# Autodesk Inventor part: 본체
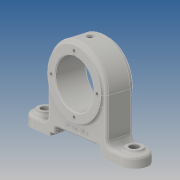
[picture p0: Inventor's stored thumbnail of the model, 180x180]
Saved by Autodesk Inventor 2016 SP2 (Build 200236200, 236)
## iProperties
Created: 2019-05
Part Number: 본체
Material: Generic
Document SubType Name: Modeling
Designer: EZ
Density: 1 g/cm^3
Appearance: Default
Mass: 168.276 g
Surface Area: 320.121 cm^2
Volume: 168.276 cm^3
Author: EZ
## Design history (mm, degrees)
sketch "스케치1"
  geometry: L1 (75, 15)-(60, 15); L2 (-75, 15)-(-75, 0); L3 (-75, -15)-(-60, -15); L4 (75, -15)-(75, 0); L5 (75, 15)-(-75, -15); L6 (-75, 15)-(75, -15); L7 (60, -15)-(75, -15); L8 (75, 0)-(75, 15); L9 (60, 15)-(-60, 15); L10 (-60, -15)-(60, -15); L11 (-75, 0)-(-75, -15); L12 (-60, 15)-(-75, 15); A1 r 15 centre (60, 0) between (60, -15) and (60, 15); A2 r 15 centre (-60, 0) between (-60, 15) and (-60, -15); 3 further points
  constraints: 24 end point, 13 parallel, 6 perpendicular, 6 point on circle, 4 midpoint, 4 tangent, 3 horizontal, 2 centre point, 2 horizontal alignment
  dimensions: "d0" = 150 distance of L4.start L3.start; "d1" = 30 distance of L3.start L2.start; "d2" = 30 diameter of A1; "d3" = 30 diameter of A2
extrude "돌출1" new body sketch "스케치1" distance "d4" = 12; taper "d5" = 0 deg
sketch "스케치2"
  geometry: L1 (24, -4)-(96, -4); L2 (96, -4)-(96, 4); L3 (96, 4)-(24, 4); L4 (24, 4)-(24, -4); L5 (24, -4)-(96, 4); L6 (96, -4)-(24, 4); L7 (0, 0)-(120, 0) reference; 1 further point
  constraints: 12 end point, 2 midpoint, 2 parallel, 1 horizontal, 1 perpendicular
  dimensions: "d6" = 72 distance of L3.end L2.end; "d7" = 4 distance between parallel lines of L7 L3
extrude "돌출2" cut sketch "스케치2" stored distance "d8" = 12; taper "d9" = 0 deg
sketch "스케치3"
  geometry: L1 (30, -22)-(90, -22); L2 (90, -22)-(90, -2); L3 (90, -2)-(30, -2); L4 (30, -2)-(30, -22); L5 (30, -22)-(90, -2); L6 (90, -22)-(30, -2); L7 (96, -12)-(120, -12) reference; 1 further point
  constraints: 12 end point, 2 midpoint, 2 parallel, 1 horizontal, 1 perpendicular
  dimensions: "d10" = 60 distance of L3.end L2.end; "d11" = 10 distance between parallel lines of L7 L3
extrude "돌출3" cut sketch "스케치3" stored distance "d12" = 12; taper "d13" = 0 deg
sketch "스케치4"
  geometry: L1 (-60, -15)-(60, -15) reference; L2 (60, 15)-(-60, 15) reference; C1 r 9 at (-60, 0); C2 r 9 at (60, 0); A1 r 15 centre (-60, 0) between (-60, 15) and (-60, -15) reference; A2 r 15 centre (60, 0) between (60, -15) and (60, 15) reference; 1 further point
  constraints: 2 centre point, 2 coincident
  dimensions: "d14" = 18 diameter of C1; "d15" = 18 diameter of C2
extrude "돌출4" join sketch "스케치4" distance "d16" = 3; taper "d17" = 0 deg
hole "구멍1" diameter "d20" = 11; stored, may be unused: countersink angle "d24" = 90 deg, drill point angle "d26" = 118 deg; dims "d21" = 6, "d22" = 4, "d23" = 2, "d25" = 8, "d27" = 10, "d28" = 10
sketch "스케치5"
  geometry: L1 (-36, 0)-(-60, 0) reference; C1 r 40 at (0, 60); 1 further point
  constraints: 1 centre point, 1 vertical alignment
  dimensions: "d29" = 60 distance from line of C1.centre L1; "d30" = 100 dimension on C1 L1
extrude "돌출5" join sketch "스케치5" stored distance "d31" = 30; taper "d32" = 0 deg
sketch "스케치6"
  geometry: L1 (30, 4)-(30, 10) reference; L2 (30, 10)-(-30, 10) reference; L3 (-30, 10)-(-30, 4) reference; L4 (-30, 4)-(-36, 4) reference; L5 (-36, 4)-(-36, 0) reference; L6 (-36, 0)-(-60, 0) reference; L7 (-60, 0)-(-60, 12) reference; L8 (60, 12)-(-60, 12) reference; L9 (60, 0)-(60, 12) reference; L10 (60, 0)-(36, 0) reference; L11 (36, 0)-(36, 4) reference; L12 (36, 4)-(30, 4) reference; L13 (-40, 60)-(-40, 12); L14 (40, 60)-(40, 12); A1 r 40 centre (0, 60) between (-40, 60) and (40, 60) reference; 1 further point
  constraints: 4 end point, 2 point on circle, 2 point on line, 2 tangent, 1 perpendicular, 1 vertical
extrude "돌출6" join sketch "스케치6" stored distance "d33" = 30; taper "d34" = 0 deg
sketch "스케치7"
  geometry: L1 (30, 4)-(30, 10) reference; L2 (30, 10)-(-30, 10) reference; L3 (-30, 10)-(-30, 4) reference; L4 (-30, 4)-(-36, 4) reference; L5 (-36, 4)-(-36, 0) reference; L6 (-36, 0)-(-60, 0) reference; L7 (-60, 0)-(-60, 12) reference; L8 (-40, 12)-(-60, 12) reference; L9 (-40, 12)-(-40, 60) reference; L10 (40, 60)-(40, 12) reference; L11 (60, 12)-(40, 12) reference; L12 (60, 0)-(60, 12) reference; L13 (60, 0)-(36, 0) reference; L14 (36, 0)-(36, 4) reference; L15 (36, 4)-(30, 4) reference; C1 r 36 at (0, 60); A1 r 40 centre (0, 60) between (40, 60) and (-40, 60) reference; 1 further point
  constraints: 1 centre point, 1 coincident
  dimensions: "d35" = 72 diameter of C1
extrude "돌출7" join sketch "스케치7" stored distance "d36" = 36; taper "d37" = 0 deg
hole "구멍2" diameter "d40" = 52; stored, may be unused: countersink angle "d44" = 90 deg, drill point angle "d46" = 118 deg; dims "d38" = 10, "d39" = 10, "d41" = 6, "d42" = 4, "d43" = 2, "d45" = 8
sketch "스케치8"
  geometry: C1 r 26 at (0, 0) reference; C2 r 36 at (0, 0) reference; A1 r 31 centre (0, 0) between (0, 31) and (0, -31); 3 further points
  constraints: 4 point on circle, 2 horizontal alignment, 2 vertical alignment, 1 centre point, 1 coincident
  dimensions: "d47" = 62 diameter of A1
hole "구멍3" sketch "스케치8" at (0, 31), (0, -31), (31, 0), (-31, 0) diameter "d48" = 3.242; stored, may be unused: countersink angle "d52" = 90 deg, drill point angle "d54" = 118 deg; dims "d49" = 6, "d50" = 4, "d51" = 2, "d53" = 8
node "작업 평면1"
sketch "스케치9"
  geometry: 2 further points
  constraints: 1 coincident
hole "구멍4" sketch "스케치9" at (0, 0) diameter "d56" = 7; stored, may be unused: countersink angle "d60" = 90 deg, drill point angle "d62" = 0 deg; dims "d57" = 6, "d58" = 7, "d59" = 2, "d61" = 1
hole "구멍5" diameter "d65" = 4.917; stored, may be unused: countersink angle "d69" = 90 deg, drill point angle "d71" = 118 deg; dims "d66" = 7, "d67" = 7, "d68" = 2, "d70" = 9, "d103" = 10, "d104" = 10
hole "구멍6" diameter "d74" = 2; stored, may be unused: countersink angle "d78" = 90 deg, drill point angle "d80" = 118 deg; dims "d75" = 2, "d76" = 7, "d77" = 2, "d79" = 10, "d81" = 10, "d82" = 10
fillet "모깎기1" dims "d86" = 6
fillet "모깎기2" dims "d87" = 3
fillet "모깎기3" dims "d88" = 3
fillet "모깎기4" dims "d89" = 3
sketch "스케치10"
  geometry: 3 further points
  constraints: 2 vertical alignment, 1 other
hole "구멍7" sketch "스케치10" at (0, 86) diameter "d90" = 3; stored, may be unused: countersink angle "d94" = 90 deg, drill point angle "d96" = 118 deg; dims "d91" = 2, "d92" = 7, "d93" = 2, "d95" = 10
chamfer "모따기2" distance "d97" = 1; stored, may be unused: second distance "d98" = 2, angle "d99" = 45 deg
sketch "스케치11"
  geometry: L1 (33, 10)-(87, 10) reference; 2 further points
  constraints: 1 vertical alignment, 1 other
  dimensions: "d100" = 7 distance from line of point (60, 17) L1
feature "엠보싱1" sketch "스케치11" dims "d0" = 150, "d1" = 30, "d2" = 30, "d3" = 30, "d6" = 72, "d7" = 4, "d101" = 0.5, "d102" = 0
node "솔리드1"
mirror "대칭1"
mirror "대칭2"
node "투영된 루프1"
node "투영된 루프2"
node "투영된 루프3"
node "투영된 루프4"
node "투영된 루프5"
